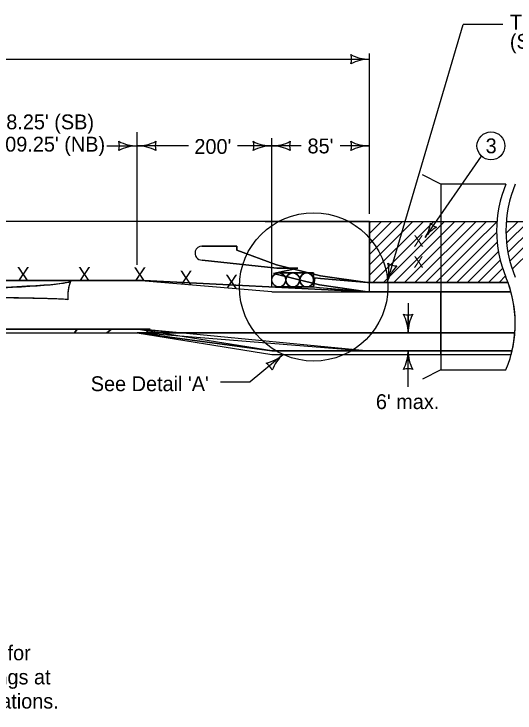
# Model space of a CAD drawing. Extents: x 10124 to 16850, y 7924 to 12166.
# Drawn here: x 12139 to 12678, y 8833 to 9587 of the extents above; entities that cross this region are included whole.
import ezdxf

# ---------------------------------------------------------------- set-up
doc = ezdxf.new("R2010")
doc.units = 0
for name, color, linetype in [('dsnShtPlotShapeBatchPrint', 7, 'Continuous'), ('dsnStdLabel', 7, 'Continuous'), ('dsnStdLineWork', 7, 'Continuous'), ('dsnStdShading', 7, 'Continuous'), ('Level 2', 7, 'Continuous'), ('SheetText', 7, 'Continuous')]:
    doc.layers.add(name, color=color, linetype=linetype)

# ---------------------------------------------------------------- blocks, each defined once
blk = doc.blocks.new('LT')
at = {"layer": 'dsnStdLabel'}
for centre, radius, start, end in [((-3.564, 0), 1.642, 342.26665, 17.73335), ((0, 4.25), 4.25, 241.92751, 270), ((0, -4.25), 4.25, 90, 118.07249)]:
    blk.add_arc(centre, radius, start, end, dxfattribs=at)

msp = doc.modelspace()

# ---------------------------------------------------------------- linework, layer by layer
at = {"layer": 'dsnShtPlotShapeBatchPrint'}
msp.add_circle((12652.43, 9444.45), 15, dxfattribs=at)
at = {"layer": 'dsnStdLabel'}
for p, q in [((12521.69, 9363.04), (12521.69, 9297.31)), ((12521.69, 9316.23), (12568.5, 9363.04)), ((12521.69, 9304.92), (12579.81, 9363.04)), ((12521.69, 9361.48), (12523.25, 9363.04)), ((12521.69, 9350.17), (12534.56, 9363.04)), ((12521.69, 9338.86), (12545.87, 9363.04)), ((12521.69, 9327.54), (12557.19, 9363.04)), ((12525.39, 9297.31), (12591.13, 9363.04)), ((12536.71, 9297.31), (12602.44, 9363.04)), ((12548.02, 9297.31), (12613.76, 9363.04)), ((12559.34, 9297.31), (12625.07, 9363.04)), ((12570.65, 9297.31), (12636.38, 9363.04)), ((12581.96, 9297.31), (12647.7, 9363.04)), ((12632.46, 9359.08), (12636.42, 9363.04)), ((12633.24, 9337.27), (12659.01, 9363.04)), ((12668.66, 9350.06), (12681.64, 9363.04)), ((12668.91, 9361.63), (12670.32, 9363.04)), ((12669.34, 9339.43), (12692.95, 9363.04)), ((12670.77, 9329.54), (12704.27, 9363.04)), ((12672.82, 9320.28), (12715.58, 9363.04)), ((12675.42, 9311.57), (12726.89, 9363.04)), ((12604.59, 9297.31), (12658.64, 9351.36)), ((12593.28, 9297.31), (12633.24, 9337.27)), ((12615.9, 9297.31), (12659.22, 9340.62)), ((12627.22, 9297.31), (12660.57, 9330.66)), ((12638.53, 9297.31), (12662.55, 9321.33)), ((12649.85, 9297.31), (12665.09, 9312.55)), ((12661.16, 9297.31), (12668.12, 9304.27)), ((12416.42, 9223.54), (12270.56, 9247.02))]:
    msp.add_line(p, q, dxfattribs=at)
for centre in [(12424.08, 9299.95), (12439.08, 9299.95), (12454.09, 9299.95)]:
    msp.add_circle(centre, 7.5, dxfattribs=at)
at = {"layer": 'dsnStdLineWork'}
for p, q in [((12598.63, 9403.04), (12578.63, 9413.04)), ((11613.92, 9299.31), (12271.67, 9299.31)), ((12416.42, 9287.31), (12271.67, 9299.31)), ((12519.73, 9297.31), (12670.86, 9297.31)), ((12416.42, 9287.31), (12519.73, 9287.31)), ((12674.03, 9287.31), (12519.73, 9287.31)), ((12080.45, 9247.02), (12270.56, 9247.02)), ((12271.76, 9243.04), (12500.59, 9243.04)), ((12500.59, 9243.04), (12678.24, 9243.04)), ((12416.42, 9223.54), (12675.23, 9223.54)), ((12598.63, 9203.04), (12578.63, 9193.04))]:
    msp.add_line(p, q, dxfattribs=at)
for points in [[(12668.63, 9403.04), (12598.63, 9403.04), (12598.63, 9203.04), (12668.63, 9203.04)], [(12462.85, 9302.29), (12461.59, 9292.44), (12461.59, 9292.44)], [(12462.85, 9302.29), (12469.08, 9301.48), (12519.73, 9297.31)], [(12461.59, 9292.44), (12467.82, 9291.64), (12519.73, 9287.31)]]:
    msp.add_lwpolyline(points, dxfattribs=at)
for centre, start, end in [((12788.62, 9353.04), 157.38014, 202.61987), ((12798.62, 9353.04), 157.38014, 202.61987), ((12548.63, 9253.04), 337.38014, 22.61987)]:
    msp.add_arc(centre, 130, start, end, dxfattribs=at)
at = {"layer": 'dsnStdShading'}
for p, q in [((12409.55, 9363.04), (11195.19, 9363.04)), ((12409.55, 9363.04), (12659.01, 9363.04)), ((12669.01, 9363.04), (13235.94, 9363.04)), ((12521.69, 9338.86), (12521.69, 9350.17)), ((12378.85, 9331.96), (12378.85, 9336.32)), ((12421.93, 9312.8), (12341.46, 9321.32)), ((12341.46, 9321.32), (12421.93, 9312.8)), ((12436.95, 9312.8), (12422.2, 9312.8)), ((12422.2, 9312.8), (12436.95, 9312.8)), ((12444.57, 9312.8), (12437.19, 9312.8)), ((12437.19, 9312.8), (12444.57, 9312.8)), ((12521.69, 9304.92), (12521.69, 9316.23)), ((12438.7, 9307.46), (12424.09, 9307.46)), ((12453.71, 9307.46), (12438.7, 9307.46)), ((12461.6, 9307.46), (12453.71, 9307.46)), ((12461.6, 9300.35), (12461.6, 9307.46)), ((12521.69, 9297.31), (12521.69, 9304.92)), ((11717.23, 9299.31), (12245.88, 9299.31)), ((12278.68, 9299.31), (11717.23, 9299.31)), ((12200.09, 9298.9), (12199.48, 9297.37)), ((12245.89, 9299.31), (12278.68, 9299.31)), ((12278.68, 9299.31), (12519.73, 9287.31)), ((12519.73, 9287.31), (12278.68, 9299.31)), ((12462.85, 9302.29), (12461.59, 9292.44)), ((12461.6, 9292.46), (12461.6, 9299.96)), ((12670.86, 9297.31), (12519.73, 9297.31)), ((12521.69, 9287.21), (12521.69, 9297.31)), ((12424.48, 9292.46), (12439.05, 9292.46)), ((12439.49, 9292.46), (12454.49, 9292.46)), ((12454.49, 9292.46), (12461.6, 9292.46)), ((12519.73, 9287.31), (12674.03, 9287.31)), ((12598.63, 9287.31), (12519.73, 9287.31)), ((12519.73, 9287.31), (12521.69, 9287.21)), ((12674.03, 9287.31), (12598.63, 9287.31)), ((12598.63, 9287.31), (12598.63, 9243.04)), ((12598.63, 9243.04), (12598.63, 9287.31)), ((12563.27, 9243.04), (12563.27, 9262.26)), ((11554.23, 9243.04), (12204.02, 9243.04)), ((12206.99, 9247.04), (11557.47, 9247.04)), ((11730.47, 9243.04), (12280.49, 9243.04)), ((12285.54, 9247.04), (11733.4, 9247.04)), ((12204.02, 9243.04), (12206.99, 9247.04)), ((12206.99, 9247.04), (12204.02, 9243.04)), ((12204.02, 9243.04), (12238.97, 9243.04)), ((12243.81, 9247.04), (12206.99, 9247.04)), ((12243.81, 9247.04), (12238.97, 9243.04)), ((12238.97, 9243.04), (12243.81, 9247.04)), ((12271.84, 9243.04), (12271.76, 9243.04)), ((12271.76, 9243.04), (12416.42, 9219.54)), ((12271.76, 9243.04), (12416.42, 9219.54)), ((12416.42, 9223.54), (12271.84, 9243.04)), ((12500.59, 9243.04), (12271.84, 9243.04)), ((12271.84, 9243.04), (12416.42, 9223.54)), ((12274.58, 9247.02), (12315.74, 9243.04)), ((12317.1, 9243.04), (12275.78, 9243.04)), ((12275.78, 9243.04), (12282.09, 9242.43)), ((12317.1, 9243.04), (12275.99, 9247.04)), ((12280.49, 9243.04), (12285.54, 9247.04)), ((12315.74, 9243.04), (12317.1, 9243.04)), ((12517.65, 9223.54), (12317.1, 9243.04)), ((12317.1, 9243.04), (12500.59, 9243.04)), ((12678.24, 9243.04), (12598.63, 9243.04)), ((12598.63, 9243.04), (12598.63, 9223.54)), ((12598.63, 9243.04), (12678.24, 9243.04)), ((12598.63, 9223.54), (12598.63, 9243.04)), ((12282.09, 9242.43), (12517.65, 9223.54)), ((12563.27, 9223.54), (12416.42, 9223.54)), ((12416.42, 9223.54), (12553.46, 9223.54)), ((12517.65, 9223.54), (12675.23, 9223.54)), ((12553.46, 9223.54), (12563.27, 9223.54)), ((12571.27, 9223.54), (12563.27, 9223.54)), ((12563.27, 9223.54), (12571.27, 9223.54)), ((12598.63, 9223.54), (12571.27, 9223.54)), ((12571.27, 9223.54), (12598.63, 9223.54)), ((12598.63, 9223.54), (12675.23, 9223.54)), ((12598.63, 9219.54), (12598.63, 9223.54)), ((12598.63, 9223.54), (12598.63, 9219.54)), ((12648.89, 9223.54), (12675.23, 9223.54)), ((12416.42, 9219.54), (12674.23, 9219.54)), ((12416.42, 9219.54), (12563.08, 9219.54)), ((12563.46, 9219.54), (12598.63, 9219.54)), ((12647.89, 9219.54), (12674.23, 9219.54))]:
    msp.add_line(p, q, dxfattribs=at)
for points in [[(12521.69, 9363.04), (12481.36, 9363.04), (12409.55, 9363.04)], [(12521.69, 9350.17), (12521.69, 9361.48), (12521.69, 9363.04)], [(12341.34, 9336.32), (12341.34, 9336.32), (12371.33, 9336.32), (12371.36, 9336.32), (12378.85, 9336.32)], [(12378.85, 9336.32), (12371.33, 9336.32), (12341.34, 9336.32)], [(12378.85, 9336.32), (12378.85, 9331.96), (12378.85, 9331.96)], [(12521.69, 9316.23), (12521.69, 9327.54), (12521.69, 9338.86)], [(12378.85, 9331.96), (12421.7, 9316.36), (12468.98, 9304.44), (12519.73, 9297.31), (12521.69, 9297.31)], [(12521.69, 9297.31), (12519.73, 9297.31), (12468.98, 9304.44), (12421.7, 9316.36), (12378.85, 9331.96)], [(12519.73, 9287.31), (12467.8, 9294.56), (12418.28, 9306.97), (12444.57, 9312.8)], [(12444.57, 9312.8), (12418.28, 9306.97), (12467.8, 9294.56), (12519.73, 9287.31)], [(12438.7, 9307.45), (12438.7, 9307.46)], [(12438.7, 9307.46), (12438.7, 9307.45)], [(12453.71, 9307.45), (12453.71, 9307.46)], [(12453.71, 9307.46), (12453.71, 9307.45)], [(12200.14, 9298.86), (12200.08, 9298.89)], [(12245.88, 9299.31), (12245.88, 9299.31), (12246.13, 9299.64)], [(12431.58, 9300.35), (12431.6, 9300.35)], [(12446.59, 9300.35), (12446.61, 9300.35)], [(12461.59, 9300.35), (12461.6, 9300.35)], [(12519.73, 9297.31), (12469.08, 9301.48), (12462.85, 9302.29)], [(12424.48, 9292.47), (12424.48, 9292.46)], [(12439.49, 9292.47), (12439.49, 9292.46)], [(12454.49, 9292.47), (12454.49, 9292.46)], [(12454.49, 9292.46), (12454.49, 9292.47)], [(12461.59, 9292.44), (12467.82, 9291.64), (12519.38, 9287.34), (12519.73, 9287.31)], [(12519.73, 9287.31), (12519.73, 9287.31)], [(11557.45, 9247.02), (12276.53, 9247.02), (12274.58, 9247.02)], [(12238.97, 9243.04), (12275.78, 9243.04), (12317.1, 9243.04)], [(12275.99, 9247.04), (12275.02, 9247.04), (12243.81, 9247.04)], [(12598.63, 9243.04), (12571.27, 9243.04), (12563.27, 9243.04), (12552.45, 9243.04), (12500.59, 9243.04)], [(12500.59, 9243.04), (12552.45, 9243.04), (12563.27, 9243.04)], [(12563.27, 9243.04), (12571.27, 9243.04), (12598.63, 9243.04)], [(12675.23, 9223.54), (12648.89, 9223.54), (12598.63, 9223.54)], [(12598.63, 9219.54), (12647.89, 9219.54), (12674.23, 9219.54)]]:
    msp.add_lwpolyline(points, dxfattribs=at)
for centre, radius, start, end in [((12341.34, 9328.82), 7.5, 90, 163.05255), ((12341.34, 9328.82), 7.5, 90, 163.05255), ((12341.34, 9328.82), 7.5, 163.04978, 270.9263), ((12341.34, 9328.82), 7.5, 163.04978, 270.9263), ((12422.07, 9320.3), 7.5, 268.97742, 271.02258), ((12422.07, 9320.3), 7.5, 268.97742, 271.02258), ((12437.07, 9320.3), 7.5, 269.06509, 270.93491), ((12437.07, 9320.3), 7.5, 269.06509, 270.93491), ((12424.09, 9299.96), 7.5, 3.00007, 92.99993), ((12424.09, 9299.96), 7.5, 2.99574, 90), ((12439.09, 9299.96), 7.5, 93.04482, 93), ((12439.09, 9299.96), 7.5, 93.04172, 177.01242), ((12439.09, 9299.96), 7.5, 2.99574, 92.9969), ((12454.1, 9299.96), 7.5, 93.00604, 182.99396), ((12454.1, 9299.96), 7.5, 92.9969, 177.01242), ((12454.09, 9299.95), 7.51, 3.1005, 92.8995), ((12454.1, 9299.96), 7.5, 2.99593, 92.9969), ((12238.3, 9282.49), 41.52, 156.77867, 185.48242), ((12239.28, 9282.47), 42.5, 159.48606, 185.32967), ((12239.28, 9282.47), 42.5, 157.25718, 157.27479), ((12280.47, 9274.6), 42.5, 143.91819, 144.46106), ((12211.79, 9324.68), 42.5, 323.88298, 323.90058), ((12280.47, 9274.6), 42.5, 143.90058, 143.90114), ((12424.07, 9300), 7.55, 273.14031, 356.68109), ((12424.07, 9300), 7.55, 317.82762, 356.66631), ((12439.09, 9299.96), 7.5, 183.01314, 269.67748), ((12439.07, 9300), 7.55, 273.14439, 356.67701), ((12439.07, 9300), 7.55, 318.90204, 356.5996), ((12454.1, 9299.96), 7.5, 182.99578, 273.00422), ((12454.1, 9299.96), 7.5, 183.08128, 273.00246), ((12454.1, 9299.96), 7.5, 272.99981, 3.00019), ((12454.1, 9299.96), 7.5, 273.00246, 0), ((12548.63, 9253.04), 130, 15.28231, 19.90723), ((12424.09, 9299.96), 7.5, 273.00246, 317.97075), ((12439.09, 9299.96), 7.5, 272.99983, 319.05414), ((12548.63, 9253.04), 130, 355.58827, 15.28231), ((12563.27, 9278.68), 16.42, 252.26665, 270), ((12520.77, 9243.04), 42.5, 0.0176, 28.07249), ((12605.77, 9243.04), 42.5, 179.9824, 180), ((12548.63, 9253.04), 130, 346.88165, 355.58827), ((12520.77, 9223.54), 42.5, 354.59945, 360), ((12520.77, 9223.54), 42.5, 359.9824, 360), ((12605.77, 9223.54), 42.5, 180.0176, 185.40055), ((12548.63, 9253.04), 130, 345.06444, 346.88165)]:
    msp.add_arc(centre, radius, start, end, dxfattribs=at)
for centre, major_axis, ratio, start_param, end_param in [((6673.95, 9331.8), (5526.17, -32.74), 0.008175, 5.82835, 6.279465), ((8643.82, 9315.33), (3556.3, -16.26), 0.011041, 5.788962, 6.278612), ((9224.44, 9266.84), (2972.56, 11.64), 0.003601, 0.004187, 0.623197), ((9959.04, 9266.04), (2237.97, 12.43), 0.004792, 0.005553, 0.624564)]:
    msp.add_ellipse(centre, major_axis=major_axis, ratio=ratio, start_param=start_param, end_param=end_param, dxfattribs=at)
at = {"layer": 'Level 2'}
for p, q in [((12424.08, 9307.45), (12461.59, 9307.45)), ((12461.59, 9307.45), (12461.59, 9292.44)), ((12461.59, 9292.44), (12424.08, 9292.44))]:
    msp.add_line(p, q, dxfattribs=at)
for centre in [(12424.08, 9299.95), (12424.08, 9299.95), (12439.08, 9299.95), (12439.08, 9299.95), (12454.09, 9299.95), (12454.09, 9299.95)]:
    msp.add_circle(centre, 7.5, dxfattribs=at)
at = {"layer": 'SheetText'}
for p, q in [((12540.78, 9297.31), (12622.54, 9575.35)), ((12665.38, 9575.35), (12622.54, 9575.35)), ((12044.69, 9537.75), (12521.69, 9537.75)), ((12521.69, 9371.04), (12521.69, 9543.8)), ((12271.76, 9316.27), (12271.76, 9459.3)), ((12416.42, 9291.86), (12416.42, 9452.84)), ((12238.76, 9444.33), (12271.76, 9444.33)), ((12326.93, 9444.33), (12271.76, 9444.33)), ((12416.42, 9444.32), (12379.63, 9444.33)), ((12447.99, 9444.32), (12416.42, 9444.32)), ((12521.69, 9444.32), (12490.12, 9444.32)), ((12581.59, 9345.78), (12642.27, 9433.41)), ((12563.27, 9275.04), (12563.27, 9243.04)), ((12552.45, 9243.04), (12571.27, 9243.04)), ((12553.46, 9223.54), (12571.27, 9223.54)), ((12563.27, 9184.78), (12563.27, 9223.54)), ((12428.68, 9219.52), (12393.35, 9190.32)), ((12361.35, 9190.32), (12393.35, 9190.32))]:
    msp.add_line(p, q, dxfattribs=at)
msp.add_circle((12461.59, 9292.44), 80, dxfattribs=at)
for centre, radius, start, end in [((12486.05, 9537.75), 16.42, 342.26665, 17.73335), ((12521.69, 9580.25), 42.5, 241.92751, 270), ((12521.69, 9495.25), 42.5, 90, 118.07249), ((12236.12, 9444.33), 16.42, 342.26665, 17.73335), ((12271.76, 9486.83), 42.5, 241.92751, 270), ((12271.76, 9486.83), 42.5, 270, 298.07249), ((12307.4, 9444.33), 16.42, 162.26665, 197.73335), ((12380.79, 9444.32), 16.42, 342.26665, 17.73335), ((12416.42, 9486.82), 42.5, 241.92751, 270), ((12416.42, 9486.82), 42.5, 270, 298.07249), ((12452.06, 9444.32), 16.42, 162.26665, 197.73335), ((12486.05, 9444.32), 16.42, 342.26665, 17.73335), ((12521.69, 9486.82), 42.5, 241.92751, 270), ((12271.76, 9401.83), 42.5, 90, 118.07249), ((12271.76, 9401.83), 42.5, 61.92751, 90), ((12416.42, 9401.82), 42.5, 90, 118.07249), ((12416.42, 9401.82), 42.5, 61.92751, 90), ((12521.69, 9401.82), 42.5, 90, 118.07249), ((12500, 9309.3), 42.5, 343.61306, 11.68555), ((12581.55, 9285.32), 42.5, 135.54057, 163.61306), ((12550.83, 9331.5), 16.42, 235.87971, 271.34641), ((12563.27, 9278.68), 16.42, 252.26665, 287.73335), ((12520.77, 9243.04), 42.5, 360, 28.07249), ((12605.77, 9243.04), 42.5, 151.92751, 180), ((12520.77, 9223.54), 42.5, 331.92751, 360), ((12605.77, 9223.54), 42.5, 180, 208.07249), ((12400.77, 9251.58), 42.5, 282.97403, 311.04652), ((12456.59, 9187.47), 42.5, 131.04652, 159.11901), ((12401.81, 9196.12), 16.42, 23.31317, 58.77987), ((12563.27, 9187.9), 16.42, 72.26665, 107.73335)]:
    msp.add_arc(centre, radius, start, end, dxfattribs=at)

# ---------------------------------------------------------------- block references
at = {"layer": 'SheetText', "xscale": 7.999600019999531, "yscale": 7.999200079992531, "rotation": -124.70293665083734}
msp.add_blockref('LT', (12581.59, 9345.78), dxfattribs=at)

# ---------------------------------------------------------------- texts
at = {"layer": 'dsnShtPlotShapeBatchPrint'}
msp.add_text('3', height=16, dxfattribs=at).set_placement((12646.72, 9436.45))
at = {"layer": 'dsnStdLabel'}
for p in [(12569.15, 9335.97), (12569.15, 9313.32)]:
    msp.add_text('X', height=12, dxfattribs=at).set_placement(p)
for p in [(12155.58, 9313.89), (12221.54, 9313.89), (12281.19, 9313.55), (12330.94, 9310.02), (12379.87, 9305.79)]:
    msp.add_text('X', height=15, rotation=180, dxfattribs=at).set_placement(p)
at = {"layer": 'SheetText'}
for s, p in [('Temporary Barrier Rail', (12672.86, 9569.7)), ('(See Typical ', (12672.86, 9548.99)), ("28.25' (SB)", (12118.76, 9462.27)), ("1209.25' (NB)", (12105.72, 9438.27)), ("200'", (12333.18, 9435.77)), ("85'", (12455.02, 9436.32)), ("See Detail 'A'", (12221.63, 9180.1)), ("6' max.", (12528.58, 9160.78)), ('Refer to TC-420 for', (11972.74, 8890.09)), ('remainder of signings at', (11949.99, 8864.09)), ('ramps and their locations.', (11942.18, 8838.09))]:
    msp.add_text(s, height=16, dxfattribs=at).set_placement(p)

doc.saveas('drawing.dxf')
